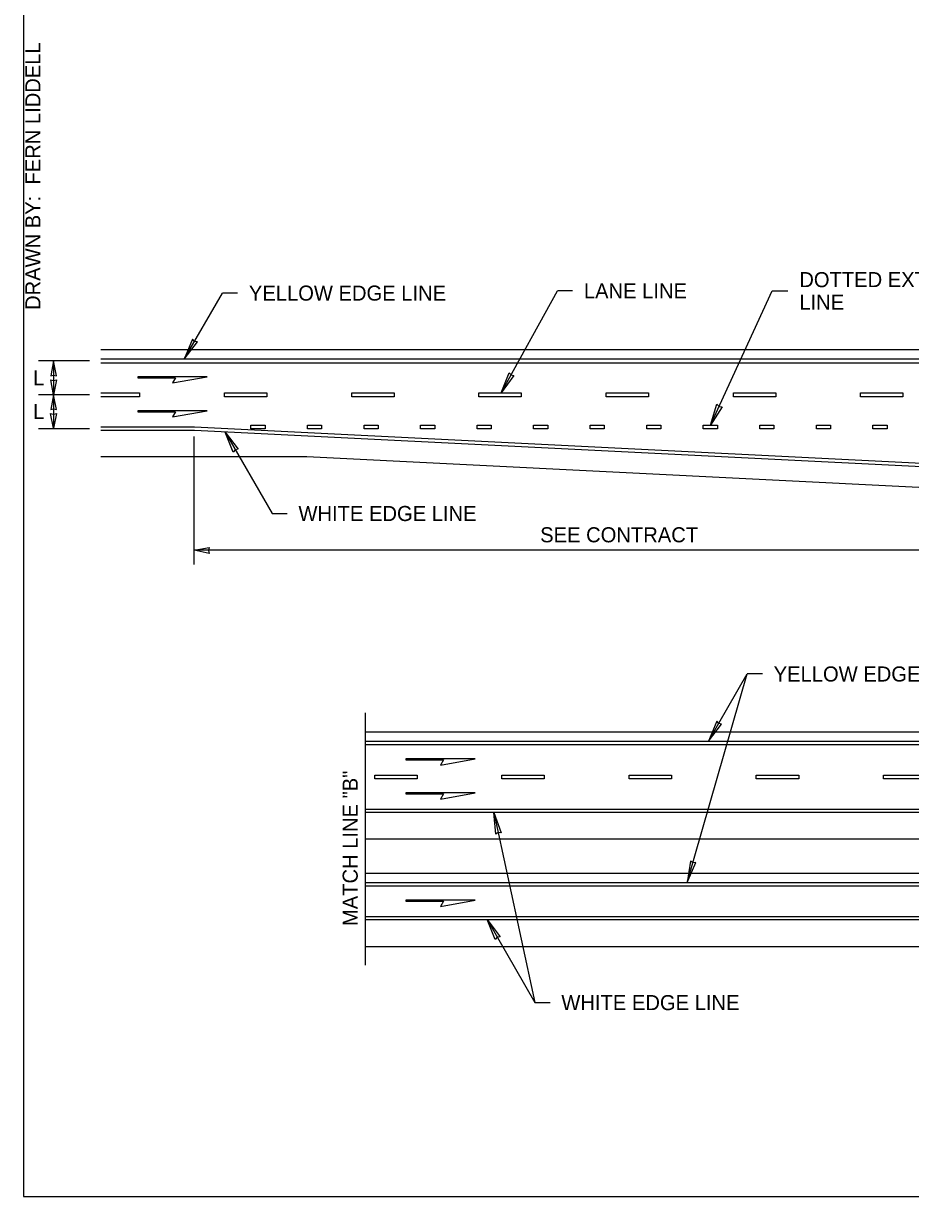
# Model space of a CAD drawing. Extents: x 99862 to 103151, y 100000 to 102076.
# Drawn here: x 99862 to 100803, y 100000 to 101245 of the extents above; entities that cross this region are included whole.
import ezdxf

# ---------------------------------------------------------------- set-up
doc = ezdxf.new("R2010")
doc.units = 0
for name, color, linetype in [('Level 1', 7, 'Continuous'), ('Level 15', 7, 'Continuous'), ('Level 2', 7, 'Continuous'), ('Level 20', 7, 'Continuous'), ('Level 3', 7, 'Continuous'), ('Level 4', 7, 'Continuous'), ('Level 5', 7, 'Continuous'), ('Level 6', 7, 'Continuous'), ('Level 60', 7, 'Continuous'), ('Level 62', 7, 'Continuous')]:
    doc.layers.add(name, color=color, linetype=linetype)

msp = doc.modelspace()

# ---------------------------------------------------------------- linework, layer by layer
at = {"layer": 'Level 1'}
msp.add_lwpolyline([(99862, 99999.5), (103151, 99999.5), (103151, 102075.5), (99862, 102075.5)], close=True, dxfattribs=at)
at = {"layer": 'Level 15'}
for p, q in [((100032.7, 100888.6), (100073.2, 100958.7)), ((100089.2, 100958.7), (100073.2, 100958.7)), ((100368.9, 100852.7), (100428.7, 100961)), ((100444.7, 100961), (100428.7, 100961)), ((100591.1, 100818.6), (100656.6, 100961)), ((100656.6, 100961), (100673.3, 100961)), ((99932, 100886.7), (99878, 100886.7)), ((99932, 100886.7), (99878, 100886.7)), ((99894, 100886.7), (99894, 100851)), ((99894, 100886.7), (99894, 100851)), ((99932, 100850.8), (99878, 100850.8)), ((99932, 100850.8), (99878, 100850.8)), ((99894, 100850.8), (99894, 100815.2)), ((99932, 100814.7), (99878, 100814.7)), ((99932, 100814.7), (99878, 100814.7)), ((100075.9, 100811.2), (100125.8, 100724.7)), ((100075.9, 100811.2), (100125.8, 100724.7)), ((100043.2, 100670.6), (100043.2, 100806.3)), ((100125.8, 100724.7), (100141.8, 100724.7)), ((100125.8, 100724.7), (100141.8, 100724.7)), ((100944.2, 100685.6), (100043.2, 100685.6)), ((100566.4, 100332.9), (100630.1, 100554.3)), ((100588.9, 100482.9), (100630.1, 100554.3)), ((100646.1, 100554.3), (100630.1, 100554.3)), ((100361.3, 100407.2), (100404.8, 100205.4)), ((100353.9, 100293.6), (100404.8, 100205.4)), ((100404.8, 100205.4), (100420.8, 100205.4))]:
    msp.add_line(p, q, dxfattribs=at)
for points in [[(100032.7, 100888.6), (100046.7, 100906.9), (100043.6, 100907.4), (100041.5, 100909.8)], [(100032.7, 100888.6), (100046.7, 100906.9), (100043.6, 100907.4), (100041.5, 100909.8)], [(99894, 100886.7), (99890.9, 100870.9), (99894, 100871.7), (99897, 100870.9)], [(100368.9, 100852.7), (100377.3, 100874.1), (100379.4, 100871.8), (100382.5, 100871.3)], [(100368.9, 100852.7), (100377.3, 100874.1), (100379.4, 100871.8), (100382.5, 100871.3)], [(99894, 100850.8), (99890.9, 100866.6), (99894, 100865.8), (99897, 100866.6)], [(99894, 100850.8), (99890.9, 100835.1), (99894, 100835.8), (99897, 100835.1)], [(100591.1, 100818.6), (100597.9, 100840.6), (100600.2, 100838.4), (100603.3, 100838.1)], [(99893.9, 100815.2), (99890.8, 100830.9), (99893.9, 100830.1), (99896.9, 100830.9)], [(100075.9, 100811.2), (100089.9, 100792.9), (100086.7, 100792.4), (100084.7, 100789.9)], [(100075.9, 100811.2), (100089.9, 100792.9), (100086.7, 100792.4), (100084.7, 100789.9)], [(100043.2, 100685.6), (100058.9, 100688.6), (100058.2, 100685.5), (100058.9, 100682.4)], [(100588.9, 100482.9), (100602.9, 100501.2), (100599.8, 100501.8), (100597.7, 100504.2)], [(100588.9, 100482.9), (100602.9, 100501.2), (100599.8, 100501.8), (100597.7, 100504.2)], [(100361.3, 100407.2), (100369, 100385.5), (100365.9, 100385.9), (100363.2, 100384.2)], [(100361.3, 100407.2), (100369, 100385.5), (100365.9, 100385.9), (100363.2, 100384.2)], [(100566.4, 100332.9), (100575.6, 100354), (100572.5, 100353.8), (100569.9, 100355.7)], [(100566.4, 100332.9), (100575.6, 100354), (100572.5, 100353.8), (100569.9, 100355.7)], [(100353.9, 100293.6), (100367.9, 100275.4), (100364.7, 100274.8), (100362.7, 100272.4)], [(100353.9, 100293.6), (100367.9, 100275.4), (100364.7, 100274.8), (100362.7, 100272.4)]]:
    msp.add_lwpolyline(points, close=True, dxfattribs=at)
at = {"layer": 'Level 2'}
for p, q in [((99944, 100898.7), (102630.3, 100898.7)), ((100224.7, 100493), (102409.4, 100493)), ((102409.4, 100379), (100224.7, 100379)), ((100224.7, 100343), (102409.4, 100343))]:
    msp.add_line(p, q, dxfattribs=at)
for points in [[(102630.3, 100670.7), (102442.8, 100670.7), (100162.8, 100784.7), (99944, 100784.7)], [(102630.3, 100670.7), (102442.8, 100670.7), (100162.8, 100784.7), (99944, 100784.7)], [(100224.7, 100265), (100876.6, 100265), (102275.7, 100125.1)]]:
    msp.add_lwpolyline(points, dxfattribs=at)
at = {"layer": 'Level 3'}
for p, q in [((102630.4, 100888.6), (99944, 100888.6)), ((99944, 100884.8), (102630.4, 100884.8)), ((100224.7, 100482.9), (102409.4, 100482.9)), ((102409.4, 100479.1), (100224.7, 100479.1)), ((100224.7, 100332.9), (102409.4, 100332.9)), ((102409.4, 100329.2), (100224.7, 100329.2))]:
    msp.add_line(p, q, dxfattribs=at)
at = {"layer": 'Level 4'}
for p, q in [((100224.7, 100410.9), (102409.4, 100410.9)), ((102409.4, 100407.2), (100224.7, 100407.2))]:
    msp.add_line(p, q, dxfattribs=at)
for points in [[(99944, 100852.7), (99985.3, 100852.7), (99985.3, 100848.7), (99944, 100848.7)], [(99944, 100852.7), (99985.3, 100852.7), (99985.3, 100848.7), (99944, 100848.7)], [(99944, 100816.6), (100043.4, 100816.6), (102323.5, 100702.6), (102630.3, 100702.6)], [(102630.3, 100698.8), (102323.3, 100698.8), (100043.4, 100812.8), (99944, 100812.8)], [(100224.7, 100296.9), (100818, 100296.9), (102278.3, 100150.9)], [(102277.9, 100147.1), (100817.6, 100293.2), (100224.7, 100293.2)]]:
    msp.add_lwpolyline(points, dxfattribs=at)
for points in [[(100075.3, 100852.7), (100120.3, 100852.7), (100120.3, 100848.7), (100075.3, 100848.7)], [(100210.3, 100852.7), (100255.3, 100852.7), (100255.3, 100848.7), (100210.3, 100848.7)], [(100345.3, 100852.7), (100390.3, 100852.7), (100390.3, 100848.7), (100345.3, 100848.7)], [(100480.3, 100852.7), (100525.3, 100852.7), (100525.3, 100848.7), (100480.3, 100848.7)], [(100615.3, 100852.7), (100660.3, 100852.7), (100660.3, 100848.7), (100615.3, 100848.7)], [(100750.3, 100852.7), (100795.3, 100852.7), (100795.3, 100848.7), (100750.3, 100848.7)], [(100103.4, 100818.6), (100118.4, 100818.6), (100118.4, 100814.6), (100103.4, 100814.6)], [(100103.4, 100818.6), (100118.4, 100818.6), (100118.4, 100814.6), (100103.4, 100814.6)], [(100163.4, 100818.6), (100178.4, 100818.6), (100178.4, 100814.6), (100163.4, 100814.6)], [(100163.4, 100818.6), (100178.4, 100818.6), (100178.4, 100814.6), (100163.4, 100814.6)], [(100223.4, 100818.6), (100238.4, 100818.6), (100238.4, 100814.6), (100223.4, 100814.6)], [(100223.4, 100818.6), (100238.4, 100818.6), (100238.4, 100814.6), (100223.4, 100814.6)], [(100283.4, 100818.6), (100298.4, 100818.6), (100298.4, 100814.6), (100283.4, 100814.6)], [(100283.4, 100818.6), (100298.4, 100818.6), (100298.4, 100814.6), (100283.4, 100814.6)], [(100343.4, 100818.6), (100358.4, 100818.6), (100358.4, 100814.6), (100343.4, 100814.6)], [(100343.4, 100818.6), (100358.4, 100818.6), (100358.4, 100814.6), (100343.4, 100814.6)], [(100403.4, 100818.6), (100418.4, 100818.6), (100418.4, 100814.6), (100403.4, 100814.6)], [(100403.4, 100818.6), (100418.4, 100818.6), (100418.4, 100814.6), (100403.4, 100814.6)], [(100463.4, 100818.6), (100478.4, 100818.6), (100478.4, 100814.6), (100463.4, 100814.6)], [(100463.4, 100818.6), (100478.4, 100818.6), (100478.4, 100814.6), (100463.4, 100814.6)], [(100523.4, 100818.6), (100538.4, 100818.6), (100538.4, 100814.6), (100523.4, 100814.6)], [(100523.4, 100818.6), (100538.4, 100818.6), (100538.4, 100814.6), (100523.4, 100814.6)], [(100583.4, 100818.6), (100598.4, 100818.6), (100598.4, 100814.6), (100583.4, 100814.6)], [(100583.4, 100818.6), (100598.4, 100818.6), (100598.4, 100814.6), (100583.4, 100814.6)], [(100643.4, 100818.6), (100658.4, 100818.6), (100658.4, 100814.6), (100643.4, 100814.6)], [(100643.4, 100818.6), (100658.4, 100818.6), (100658.4, 100814.6), (100643.4, 100814.6)], [(100703.4, 100818.6), (100718.4, 100818.6), (100718.4, 100814.6), (100703.4, 100814.6)], [(100703.4, 100818.6), (100718.4, 100818.6), (100718.4, 100814.6), (100703.4, 100814.6)], [(100763.4, 100818.6), (100778.4, 100818.6), (100778.4, 100814.6), (100763.4, 100814.6)], [(100763.4, 100818.6), (100778.4, 100818.6), (100778.4, 100814.6), (100763.4, 100814.6)], [(100234.7, 100447), (100279.7, 100447), (100279.7, 100443), (100234.7, 100443)], [(100234.7, 100447), (100279.7, 100447), (100279.7, 100443), (100234.7, 100443)], [(100369.7, 100447), (100414.7, 100447), (100414.7, 100443), (100369.7, 100443)], [(100369.7, 100447), (100414.7, 100447), (100414.7, 100443), (100369.7, 100443)], [(100504.7, 100447), (100549.7, 100447), (100549.7, 100443), (100504.7, 100443)], [(100504.7, 100447), (100549.7, 100447), (100549.7, 100443), (100504.7, 100443)], [(100639.7, 100447), (100684.7, 100447), (100684.7, 100443), (100639.7, 100443)], [(100639.7, 100447), (100684.7, 100447), (100684.7, 100443), (100639.7, 100443)], [(100774.7, 100447), (100819.7, 100447), (100819.7, 100443), (100774.7, 100443)], [(100774.7, 100447), (100819.7, 100447), (100819.7, 100443), (100774.7, 100443)]]:
    msp.add_lwpolyline(points, close=True, dxfattribs=at)
at = {"layer": 'Level 5'}
for points in [[(99983.2, 100868.7), (100023.3, 100868.7), (100020.1, 100863.3), (100057.1, 100869.8), (99983.2, 100869.8)], [(99983.2, 100832.6), (100023.3, 100832.6), (100020.1, 100827.2), (100057.1, 100833.7), (99983.2, 100833.7)], [(100267.7, 100463.1), (100307.7, 100463.1), (100304.6, 100457.6), (100341.5, 100464.1), (100267.7, 100464.1)], [(100267.7, 100427), (100307.7, 100427), (100304.6, 100421.5), (100341.5, 100428), (100267.7, 100428)], [(100267.7, 100313), (100307.7, 100313), (100304.6, 100307.6), (100341.5, 100314.1), (100267.7, 100314.1)]]:
    msp.add_lwpolyline(points, close=True, dxfattribs=at)
at = {"layer": 'Level 6'}
msp.add_line((100224.7, 100513), (100224.7, 100245), dxfattribs=at)
at = {"layer": 'Level 60'}
msp.add_line((99862, 99999.5), (99862, 99999.5), dxfattribs=at)

# ---------------------------------------------------------------- texts
at = {"layer": 'Level 20'}
for s, p in [('DOTTED EXTENSION', (100685.3, 100965)), ('YELLOW EDGE LINE', (100101.2, 100950.7)), ('LANE LINE', (100456.7, 100953)), ('LINE', (100685.3, 100941)), ('L', (99872.2, 100860.8)), ('L', (99872.2, 100825)), ('WHITE EDGE LINE', (100153.8, 100716.7)), ('SEE CONTRACT', (100410.3, 100694.1)), ('YELLOW EDGE LINE', (100658.1, 100546.3)), ('WHITE EDGE LINE', (100432.8, 100197.4))]:
    msp.add_text(s, height=16, dxfattribs=at).set_placement(p)
msp.add_text('MATCH LINE "B"', height=16, rotation=90, dxfattribs=at).set_placement((100216.7, 100286.7))
at = {"layer": 'Level 62'}
msp.add_text('DRAWN BY:  FERN LIDDELL', height=16, rotation=90, dxfattribs=at).set_placement((99880, 100940.8))

doc.saveas('drawing.dxf')
